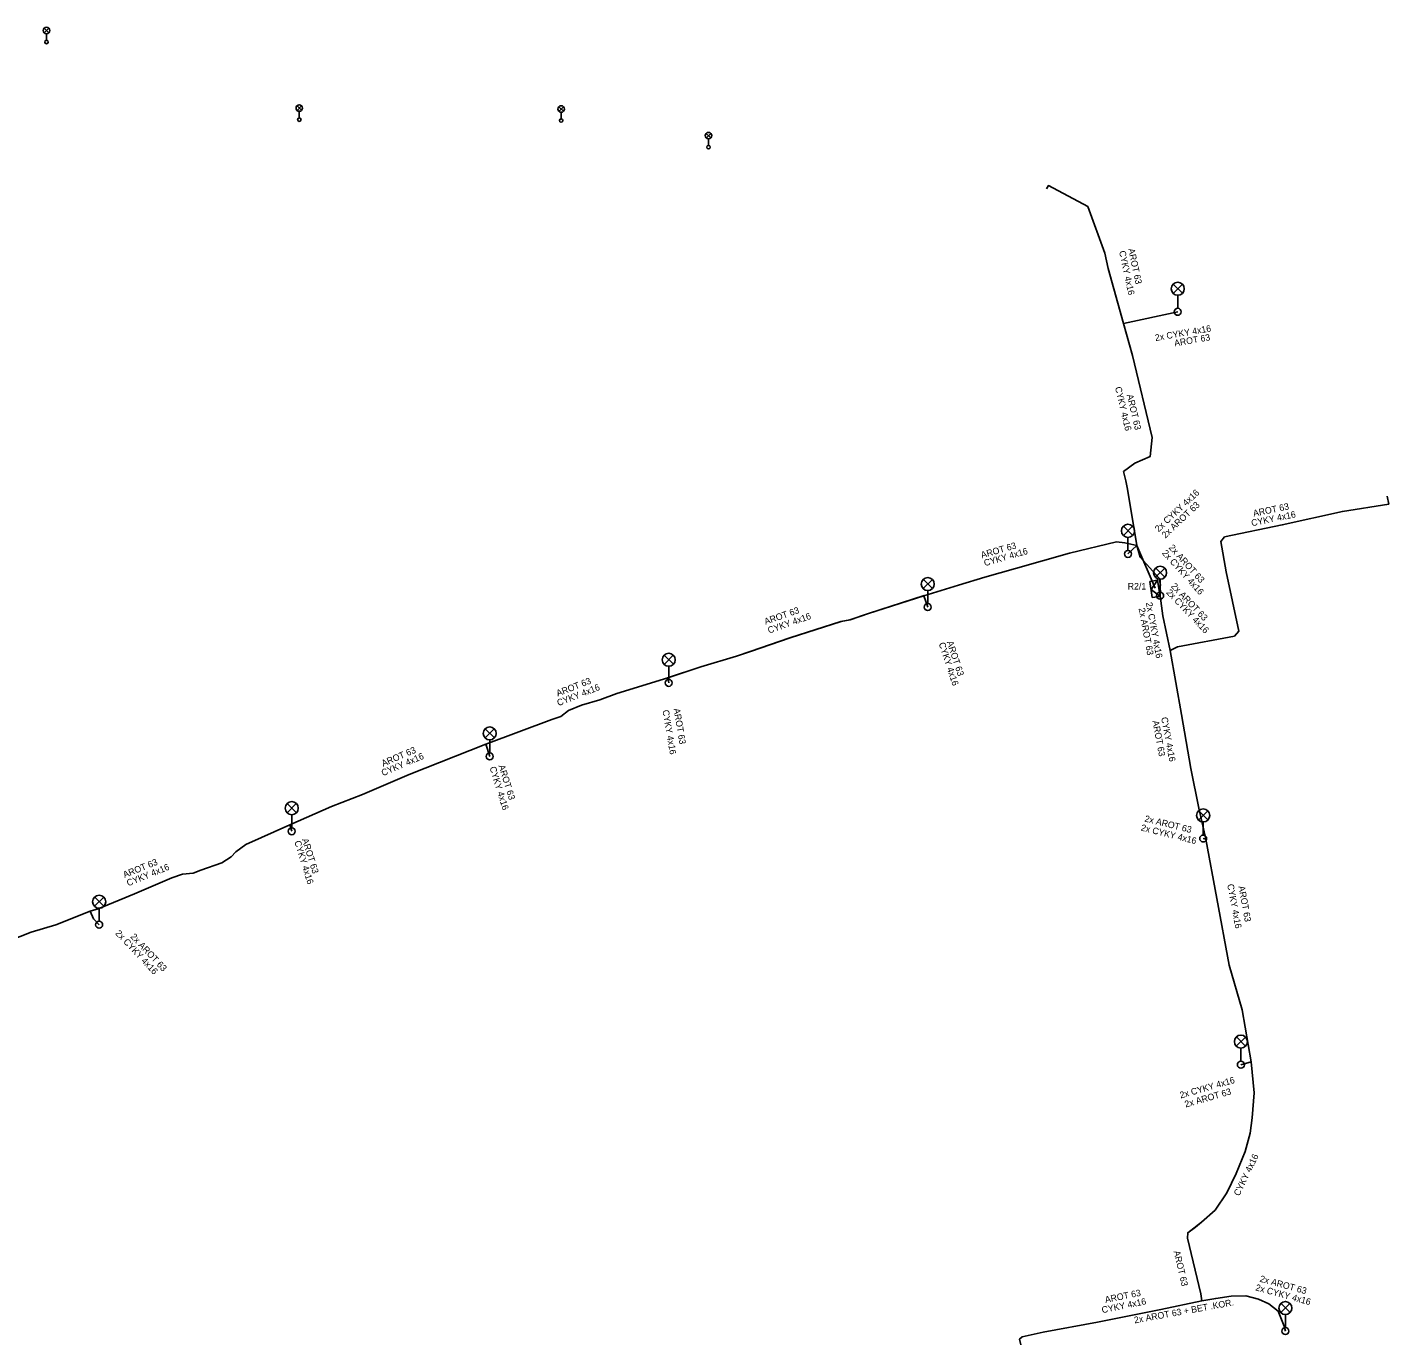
# Model space of a CAD drawing. Extents: x -641884 to -641258, y -1196509 to -1195931.
# Drawn here: x -641414.3 to -641258, y -1196087 to -1195935.7 of the extents above; entities that cross this region are included whole.
import ezdxf

# ---------------------------------------------------------------- set-up
doc = ezdxf.new("R2010")
doc.units = 0
for name, color, linetype in [('CIZÍ_NADZEM', 7, 'Continuous'), ('CIZÍ_NADZEM_POPIS', 7, 'Continuous'), ('TECH_OCHR_PÁSMO_HRAN', 7, 'Continuous'), ('Vrstva 22', 7, 'Continuous'), ('Vrstva 31', 7, 'Continuous'), ('ZP_EON', 7, 'Continuous'), ('ZP_EON_POPIS', 7, 'Continuous')]:
    doc.layers.add(name, color=color, linetype=linetype)

msp = doc.modelspace()

# ---------------------------------------------------------------- linework, layer by layer
at = {"layer": 'CIZÍ_NADZEM'}
msp.add_lwpolyline([(-641285.17, -1196001.17), (-641285.45, -1195999.32), (-641284.56, -1195999.18), (-641284.28, -1196001.04)], close=True, dxfattribs=at)
msp.add_lwpolyline([(-641284.28, -1196001.04), (-641285.31, -1196000.25), (-641284.56, -1195999.18)], dxfattribs=at)
at = {"layer": 'TECH_OCHR_PÁSMO_HRAN'}
for p, q in [((-641288.47, -1195969.69), (-641282.25, -1195968.35)), ((-641286.94, -1195995.19), (-641287.96, -1195996.15)), ((-641311.38, -1196000.95), (-641310.95, -1196002.26)), ((-641340.79, -1196010.37), (-641340.69, -1196010.96)), ((-641361.68, -1196017.99), (-641361.24, -1196019.41)), ((-641384.2, -1196027.26), (-641383.97, -1196028)), ((-641279.01, -1196028.91), (-641279.33, -1196028.83)), ((-641273.82, -1196054.47), (-641275, -1196054.81)), ((-641277.88, -1196081.65), (-641279.47, -1196081.94))]:
    msp.add_line(p, q, dxfattribs=at)
for points in [[(-641288.47, -1195969.69), (-641290.24, -1195963.36), (-641290.61, -1195961.62), (-641292.58, -1195956.27), (-641297.09, -1195953.85), (-641297.33, -1195954.22)], [(-641286.94, -1195995.19), (-641288, -1195988.71), (-641288.19, -1195987.75), (-641288.47, -1195986.7), (-641287.18, -1195985.72), (-641285.42, -1195984.98), (-641285.2, -1195982.79), (-641287.44, -1195973.38), (-641288.47, -1195969.69)], [(-641283.12, -1196007.25), (-641282.26, -1196006.84), (-641275.74, -1196005.58), (-641275.25, -1196005.03), (-641276.67, -1195998.21), (-641277.29, -1195994.72), (-641276.87, -1195994.18), (-641270.24, -1195992.82), (-641263.34, -1195991.28), (-641258.02, -1195990.42), (-641258.19, -1195989.52)], [(-641286.94, -1195995.19), (-641288.33, -1195994.87), (-641289.29, -1195994.77), (-641294.67, -1195996.08), (-641300.87, -1195997.83), (-641304.38, -1195998.84), (-641307.41, -1195999.73), (-641311.38, -1196000.95)], [(-641284.83, -1196000.1), (-641286.94, -1195995.19)], [(-641284.42, -1196000.11), (-641284.24, -1195999.75), (-641284.39, -1195998.93), (-641286.55, -1195996.54), (-641286.94, -1195995.19)], [(-641284.42, -1196000.11), (-641284.21, -1196000.33), (-641284.27, -1196000.96)], [(-641311.35, -1196000.94), (-641317.77, -1196003.01), (-641319.88, -1196003.71), (-641320.92, -1196003.92), (-641326.78, -1196005.77), (-641331.33, -1196007.37), (-641332.92, -1196007.88), (-641337.02, -1196009.1), (-641340.81, -1196010.37)], [(-641283.12, -1196007.25), (-641283.95, -1196003.25), (-641284.27, -1196000.96)], [(-641279.01, -1196028.91), (-641279.84, -1196025.33), (-641280.75, -1196020.78), (-641281.81, -1196014.61), (-641283.12, -1196007.25)], [(-641340.79, -1196010.37), (-641346.66, -1196012.19), (-641348.61, -1196012.91), (-641350.72, -1196013.51), (-641352.19, -1196014.15), (-641353.09, -1196014.84), (-641354.12, -1196015.16), (-641361.68, -1196017.99)], [(-641361.68, -1196017.99), (-641370.47, -1196021.48), (-641375.85, -1196023.78), (-641379.39, -1196025.17), (-641384.2, -1196027.26)], [(-641384.2, -1196027.26), (-641389.23, -1196029.52), (-641390.38, -1196030.36), (-641390.91, -1196030.94), (-641391.98, -1196031.64), (-641394.39, -1196032.45), (-641395.3, -1196032.8), (-641396.5, -1196032.91), (-641397.72, -1196033.33), (-641402.02, -1196035.19), (-641406.21, -1196036.89), (-641407.1, -1196037.16)], [(-641273.82, -1196054.47), (-641274.87, -1196048.52), (-641276.36, -1196043.39), (-641277.75, -1196035.73), (-641279.01, -1196028.91)], [(-641407.1, -1196037.16), (-641411.04, -1196038.74), (-641413.9, -1196039.6), (-641417.7, -1196041.09), (-641418.86, -1196041.61), (-641421.39, -1196042.78), (-641423.73, -1196043.81), (-641425.57, -1196044.59), (-641428.73, -1196045.97), (-641429.58, -1196046.27)], [(-641407.1, -1196037.16), (-641406.73, -1196038.05), (-641406.08, -1196038.74)], [(-641279.47, -1196081.94), (-641279.61, -1196081.11), (-641281.11, -1196074.73), (-641281.09, -1196074.1), (-641279.51, -1196072.9), (-641277.95, -1196071.51), (-641276.61, -1196069.52), (-641275.55, -1196067.32), (-641274.49, -1196064.76), (-641273.92, -1196062.66), (-641273.7, -1196060.91), (-641273.48, -1196058.05), (-641273.82, -1196054.47)], [(-641277.88, -1196081.65), (-641276.13, -1196081.38), (-641274.43, -1196081.34), (-641272.97, -1196081.74), (-641271.78, -1196082.25), (-641270.71, -1196083.12), (-641270.04, -1196084.83), (-641269.89, -1196085.4)], [(-641300.25, -1196086.97), (-641300.41, -1196086.32), (-641300.1, -1196086.04), (-641297.7, -1196085.53), (-641291.45, -1196084.37), (-641284.2, -1196082.9), (-641279.47, -1196081.94)]]:
    msp.add_lwpolyline(points, dxfattribs=at)
at = {"layer": 'Vrstva 31'}
for p, q in [((-641412.39, -1195936.31), (-641411.87, -1195935.78)), ((-641411.86, -1195936.3), (-641412.39, -1195935.78)), ((-641412.13, -1195936.42), (-641412.13, -1195937.17)), ((-641383.36, -1195945.22), (-641382.84, -1195944.69)), ((-641382.83, -1195945.21), (-641383.36, -1195944.69)), ((-641383.1, -1195945.33), (-641383.1, -1195946.08)), ((-641353.3, -1195945.33), (-641352.78, -1195944.8)), ((-641352.77, -1195945.32), (-641353.3, -1195944.8)), ((-641353.04, -1195945.44), (-641353.04, -1195946.19)), ((-641336.38, -1195948.39), (-641335.86, -1195947.86)), ((-641335.85, -1195948.38), (-641336.38, -1195947.86)), ((-641336.12, -1195948.5), (-641336.12, -1195949.25)), ((-641282.78, -1195966.23), (-641281.72, -1195965.17)), ((-641281.71, -1195966.22), (-641282.76, -1195965.16)), ((-641282.25, -1195966.45), (-641282.25, -1195967.95)), ((-641288.49, -1195994.03), (-641287.43, -1195992.97)), ((-641287.42, -1195994.02), (-641288.47, -1195992.96)), ((-641287.96, -1195994.25), (-641287.96, -1195995.75)), ((-641284.8, -1195998.84), (-641283.74, -1195997.78)), ((-641283.73, -1195998.83), (-641284.78, -1195997.77)), ((-641311.48, -1196000.14), (-641310.42, -1195999.08)), ((-641310.41, -1196000.13), (-641311.46, -1195999.07)), ((-641310.95, -1196000.36), (-641310.95, -1196001.86)), ((-641284.27, -1195999.06), (-641284.27, -1196000.56)), ((-641341.22, -1196008.84), (-641340.16, -1196007.78)), ((-641340.15, -1196008.83), (-641341.2, -1196007.77)), ((-641340.69, -1196009.06), (-641340.69, -1196010.56)), ((-641361.77, -1196017.29), (-641360.71, -1196016.23)), ((-641360.7, -1196017.28), (-641361.75, -1196016.22)), ((-641361.24, -1196017.51), (-641361.24, -1196019.01)), ((-641384.5, -1196025.88), (-641383.45, -1196024.82)), ((-641383.43, -1196025.87), (-641384.49, -1196024.81)), ((-641383.97, -1196026.1), (-641383.97, -1196027.6)), ((-641279.86, -1196026.71), (-641278.8, -1196025.65)), ((-641278.79, -1196026.7), (-641279.84, -1196025.64)), ((-641279.33, -1196026.93), (-641279.33, -1196028.43)), ((-641406.61, -1196036.62), (-641405.55, -1196035.56)), ((-641405.54, -1196036.61), (-641406.59, -1196035.55)), ((-641406.08, -1196036.84), (-641406.08, -1196038.34)), ((-641275.53, -1196052.69), (-641274.47, -1196051.63)), ((-641274.46, -1196052.68), (-641275.51, -1196051.62)), ((-641275, -1196052.91), (-641275, -1196054.41)), ((-641270.42, -1196083.28), (-641269.36, -1196082.22)), ((-641269.35, -1196083.27), (-641270.4, -1196082.21)), ((-641269.89, -1196083.5), (-641269.89, -1196085))]:
    msp.add_line(p, q, dxfattribs=at)
for centre, radius in [((-641412.13, -1195936.04), 0.375), ((-641412.13, -1195937.37), 0.2), ((-641383.1, -1195944.95), 0.375), ((-641353.04, -1195945.06), 0.375), ((-641383.1, -1195946.28), 0.2), ((-641353.04, -1195946.39), 0.2), ((-641336.12, -1195948.12), 0.375), ((-641336.12, -1195949.45), 0.2), ((-641282.25, -1195965.7), 0.75), ((-641282.25, -1195968.35), 0.4), ((-641287.96, -1195993.5), 0.75), ((-641287.96, -1195996.15), 0.4), ((-641310.95, -1195999.61), 0.75), ((-641284.27, -1195998.31), 0.75), ((-641310.95, -1196002.26), 0.4), ((-641284.27, -1196000.96), 0.4), ((-641340.69, -1196008.31), 0.75), ((-641340.69, -1196010.96), 0.4), ((-641361.24, -1196016.76), 0.75), ((-641361.24, -1196019.41), 0.4), ((-641383.97, -1196025.35), 0.75), ((-641279.33, -1196026.18), 0.75), ((-641383.97, -1196028), 0.4), ((-641279.33, -1196028.83), 0.4), ((-641406.08, -1196036.09), 0.75), ((-641406.08, -1196038.74), 0.4), ((-641275, -1196052.16), 0.75), ((-641275, -1196054.81), 0.4), ((-641269.89, -1196082.75), 0.75), ((-641269.89, -1196085.4), 0.4)]:
    msp.add_circle(centre, radius, dxfattribs=at)
at = {"layer": 'ZP_EON'}
for p, q in [((-641288.47, -1195969.69), (-641282.25, -1195968.35)), ((-641286.94, -1195995.19), (-641287.96, -1195996.15)), ((-641311.38, -1196000.95), (-641310.95, -1196002.26)), ((-641340.79, -1196010.37), (-641340.69, -1196010.96)), ((-641361.68, -1196017.99), (-641361.24, -1196019.41)), ((-641384.2, -1196027.26), (-641383.97, -1196028)), ((-641279.01, -1196028.91), (-641279.33, -1196028.83)), ((-641273.82, -1196054.47), (-641275, -1196054.81))]:
    msp.add_line(p, q, dxfattribs=at)
for points in [[(-641288.47, -1195969.69), (-641290.24, -1195963.36), (-641290.61, -1195961.62), (-641292.58, -1195956.27), (-641297.09, -1195953.85), (-641297.33, -1195954.22)], [(-641286.94, -1195995.19), (-641288, -1195988.71), (-641288.19, -1195987.75), (-641288.47, -1195986.7), (-641287.18, -1195985.72), (-641285.42, -1195984.98), (-641285.2, -1195982.79), (-641287.44, -1195973.38), (-641288.47, -1195969.69)], [(-641283.12, -1196007.25), (-641282.26, -1196006.84), (-641275.74, -1196005.58), (-641275.25, -1196005.03), (-641276.67, -1195998.21), (-641277.29, -1195994.72), (-641276.87, -1195994.18), (-641270.24, -1195992.82), (-641263.34, -1195991.28), (-641258.02, -1195990.42), (-641258.19, -1195989.52)], [(-641286.94, -1195995.19), (-641288.33, -1195994.87), (-641289.29, -1195994.77), (-641294.67, -1195996.08), (-641300.87, -1195997.83), (-641304.38, -1195998.84), (-641307.41, -1195999.73), (-641311.38, -1196000.95)], [(-641284.42, -1196000.11), (-641284.24, -1195999.75), (-641284.39, -1195998.93), (-641286.55, -1195996.54), (-641286.94, -1195995.19)], [(-641284.42, -1196000.11), (-641284.21, -1196000.33), (-641284.27, -1196000.96)], [(-641311.38, -1196000.95), (-641317.75, -1196003.01), (-641319.86, -1196003.71), (-641320.9, -1196003.92), (-641326.76, -1196005.77), (-641331.31, -1196007.37), (-641332.9, -1196007.88), (-641337, -1196009.1), (-641340.79, -1196010.37)], [(-641283.12, -1196007.25), (-641283.95, -1196003.25), (-641284.27, -1196000.96)], [(-641279.01, -1196028.91), (-641279.84, -1196025.33), (-641280.75, -1196020.78), (-641281.81, -1196014.61), (-641283.12, -1196007.25)], [(-641340.79, -1196010.37), (-641346.66, -1196012.19), (-641348.61, -1196012.91), (-641350.72, -1196013.51), (-641352.19, -1196014.15), (-641353.09, -1196014.84), (-641354.12, -1196015.16), (-641361.68, -1196017.99)], [(-641361.68, -1196017.99), (-641370.47, -1196021.48), (-641375.85, -1196023.78), (-641379.39, -1196025.17), (-641384.2, -1196027.26)], [(-641384.2, -1196027.26), (-641389.23, -1196029.52), (-641390.38, -1196030.36), (-641390.91, -1196030.94), (-641391.98, -1196031.64), (-641394.39, -1196032.45), (-641395.3, -1196032.8), (-641396.5, -1196032.91), (-641397.72, -1196033.33), (-641402.02, -1196035.19), (-641406.21, -1196036.89), (-641407.1, -1196037.16)], [(-641273.82, -1196054.47), (-641274.87, -1196048.52), (-641276.36, -1196043.39), (-641277.75, -1196035.73), (-641279.01, -1196028.91)], [(-641407.1, -1196037.16), (-641411.04, -1196038.74), (-641413.9, -1196039.6), (-641417.7, -1196041.09), (-641418.86, -1196041.61), (-641421.39, -1196042.78), (-641423.73, -1196043.81), (-641425.57, -1196044.59), (-641428.73, -1196045.97), (-641429.58, -1196046.27)], [(-641407.1, -1196037.16), (-641406.73, -1196038.05), (-641406.08, -1196038.74)], [(-641279.47, -1196081.94), (-641279.61, -1196081.11), (-641281.11, -1196074.73), (-641281.09, -1196074.1), (-641280.21, -1196073.46), (-641279.51, -1196072.9), (-641277.95, -1196071.51), (-641276.61, -1196069.52), (-641275.55, -1196067.32), (-641274.49, -1196064.76), (-641273.92, -1196062.66), (-641273.7, -1196060.91), (-641273.48, -1196058.05), (-641273.82, -1196054.47)], [(-641279.47, -1196081.94), (-641277.88, -1196081.65), (-641276.13, -1196081.38), (-641274.43, -1196081.34), (-641272.97, -1196081.74), (-641271.78, -1196082.25), (-641270.71, -1196083.12), (-641270.04, -1196084.83), (-641269.89, -1196085.4)], [(-641300.25, -1196086.97), (-641300.41, -1196086.32), (-641300.1, -1196086.04), (-641297.7, -1196085.53), (-641291.45, -1196084.37), (-641284.2, -1196082.9), (-641279.47, -1196081.94)]]:
    msp.add_lwpolyline(points, dxfattribs=at)

# ---------------------------------------------------------------- texts
at = {"layer": 'CIZÍ_NADZEM_POPIS'}
msp.add_text('R2/1', height=0.75, dxfattribs=at).set_placement((-641287.99, -1196000.24))
at = {"layer": 'Vrstva 22'}
for s, rotation, p in [('AROT 63', 282.0048, (-641287.94, -1195961.15)), ('AROT 63', 9.8373, (-641282.59, -1195972.33)), ('AROT 63', 283.3898, (-641288.11, -1195977.91)), ('2x AROT 63', 43.2643, (-641283.67, -1195994.4)), ('AROT 63', 11.5922, (-641273.52, -1195991.87)), ('AROT 63', 16.0531, (-641304.73, -1195996.66)), ('2x AROT 63', 312.1062, (-641283.34, -1195995.47)), ('2x AROT 63', 313.6678, (-641283.07, -1195999.92)), ('AROT 63', 19.3741, (-641329.57, -1196004.3)), ('2x AROT 63', 280.5847, (-641286.75, -1196002.42)), ('AROT 63', 288.1721, (-641308.77, -1196006.28)), ('AROT 63', 21.4377, (-641353.42, -1196012.54)), ('AROT 63', 279.6197, (-641340.14, -1196013.94)), ('AROT 63', 280.5847, (-641285.16, -1196015.35)), ('AROT 63', 23.1472, (-641373.48, -1196020.59)), ('AROT 63', 287.2161, (-641360.24, -1196020.48)), ('2x AROT 63', 345.9638, (-641286.11, -1196026.87)), ('AROT 63', 287.2658, (-641382.8, -1196028.94)), ('AROT 63', 22.0838, (-641403.16, -1196033.38)), ('AROT 63', 280.4674, (-641275.29, -1196034.34)), ('2x AROT 63', 313.2902, (-641402.55, -1196040.15)), ('2x AROT 63', 16.0736, (-641281.34, -1196059.73)), ('AROT 63', 283.2305, (-641282.73, -1196076.25)), ('2x AROT 63', 344.6785, (-641272.89, -1196079.71)), ('AROT 63', 11.4618, (-641290.53, -1196082.17)), ('2x AROT 63 + BET .KOR.', 10.3366, (-641287.19, -1196084.52))]:
    msp.add_text(s, height=0.75, rotation=rotation, dxfattribs=at).set_placement(p)
at = {"layer": 'ZP_EON_POPIS'}
for s, rotation, p in [('CYKY 4x16', 282.0048, (-641288.99, -1195961.41)), ('2x CYKY 4x16', 9.8373, (-641284.8, -1195971.71)), ('CYKY 4x16', 283.3898, (-641289.46, -1195977.04)), ('2x CYKY 4x16', 43.2643, (-641284.45, -1195993.68)), ('CYKY 4x16', 11.5922, (-641273.73, -1195992.98)), ('CYKY 4x16', 16.0531, (-641304.38, -1195997.57)), ('2x CYKY 4x16', 312.1062, (-641284.11, -1195996.09)), ('2x CYKY 4x16', 313.6678, (-641283.63, -1196000.63)), ('2x CYKY 4x16', 280.5847, (-641285.91, -1196001.77)), ('CYKY 4x16', 19.3741, (-641329.17, -1196005.31)), ('CYKY 4x16', 288.1721, (-641309.7, -1196006.44)), ('CYKY 4x16', 21.4377, (-641353.34, -1196013.64)), ('CYKY 4x16', 279.6197, (-641341.41, -1196014.12)), ('CYKY 4x16', 280.5847, (-641284.16, -1196014.96)), ('CYKY 4x16', 23.1472, (-641373.49, -1196021.68)), ('CYKY 4x16', 287.2161, (-641361.27, -1196020.69)), ('2x CYKY 4x16', 345.9638, (-641286.53, -1196027.91)), ('CYKY 4x16', 287.2658, (-641383.68, -1196029.2)), ('CYKY 4x16', 22.0838, (-641402.74, -1196034.33)), ('CYKY 4x16', 280.4674, (-641276.57, -1196034.12)), ('2x CYKY 4x16', 313.2902, (-641404.28, -1196039.77)), ('2x CYKY 4x16', 16.0736, (-641281.9, -1196058.69)), ('CYKY 4x16', 64.2744, (-641275.19, -1196069.95)), ('2x CYKY 4x16', 344.6785, (-641273.38, -1196080.71)), ('CYKY 4x16', 11.4618, (-641290.9, -1196083.35))]:
    msp.add_text(s, height=0.75, rotation=rotation, dxfattribs=at).set_placement(p)

doc.saveas('drawing.dxf')
